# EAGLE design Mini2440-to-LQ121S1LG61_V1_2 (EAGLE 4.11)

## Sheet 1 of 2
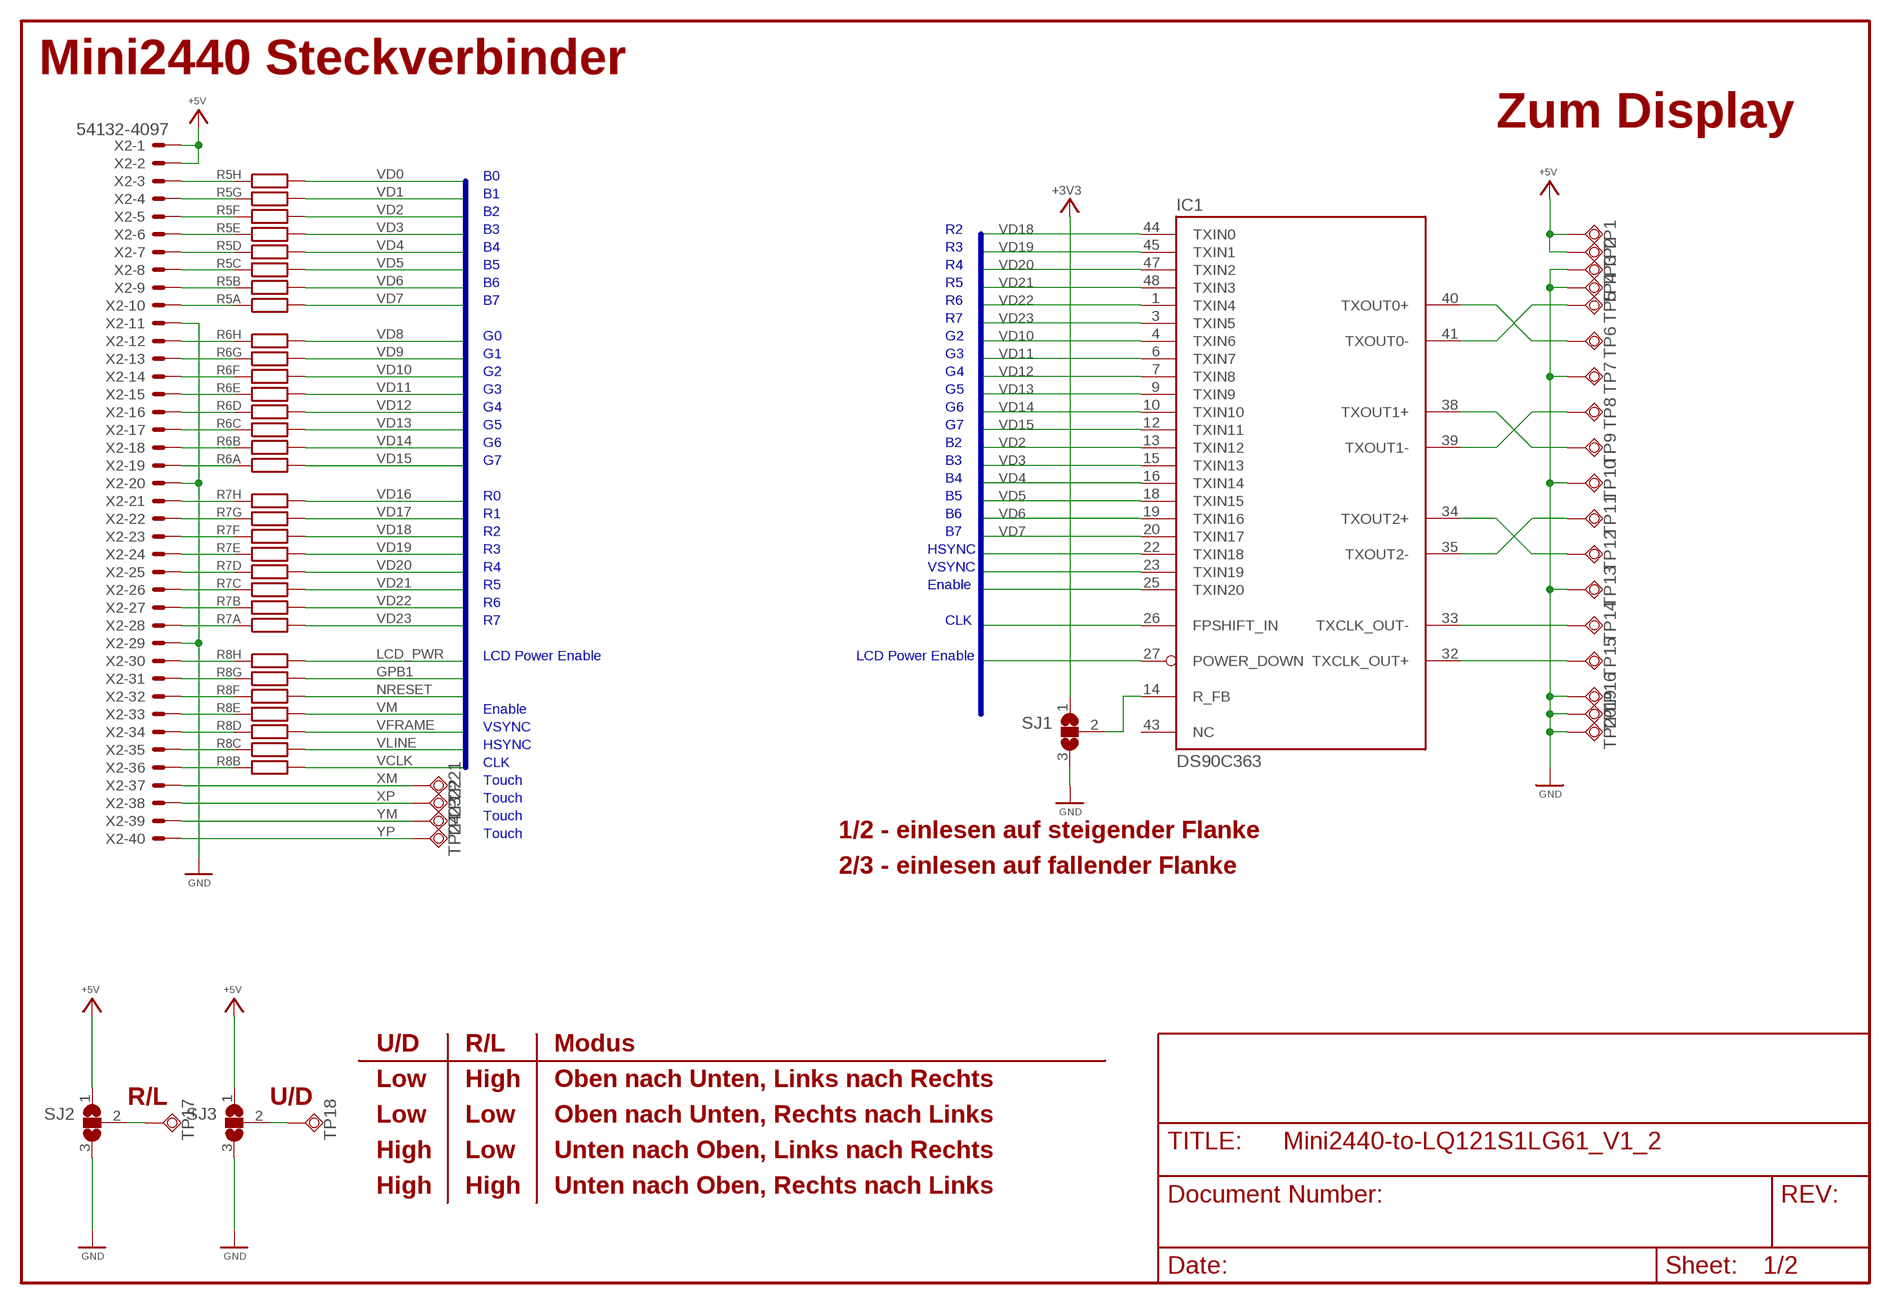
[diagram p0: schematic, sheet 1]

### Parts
IC1  DS90C363  [TSSOP48]
R5  R-8X0402  [YC248]
R6  R-8X0402  [YC248]
R7  R-8X0402  [YC248]
R8  R-8X0402  [YC248]
SJ1  SJ2WS  [SJ_2S]
SJ2  SJ2WS  [SJ_2S]
SJ3  SJ2WS  [SJ_2S]
TP1  TPSQTP15R  [TP15R]
TP2  TPSQTP15R  [TP15R]
TP3  TPSQTP15R  [TP15R]
TP4  TPSQTP15R  [TP15R]
TP5  TPSQTP15R  [TP15R]
TP6  TPSQTP15R  [TP15R]
TP7  TPSQTP15R  [TP15R]
TP8  TPSQTP15R  [TP15R]
TP9  TPSQTP15R  [TP15R]
TP10  TPSQTP15R  [TP15R]
TP11  TPSQTP15R  [TP15R]
TP12  TPSQTP15R  [TP15R]
TP13  TPSQTP15R  [TP15R]
TP14  TPSQTP15R  [TP15R]
TP15  TPSQTP15R  [TP15R]
TP16  TPSQTP15R  [TP15R]
TP17  TPSQTP15R  [TP15R]
TP18  TPSQTP15R  [TP15R]
TP19  TPSQTP15R  [TP15R]
TP20  TPSQTP15R  [TP15R]
TP21  TPSQTP12R  [TP12R]
TP22  TPSQTP12R  [TP12R]
TP23  TPSQTP12R  [TP12R]
TP24  TPSQTP12R  [TP12R]
X2  54132-4097  [54132-4097]

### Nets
+3V3: SJ1.1 ; also sheet 2
+5V: SJ2.1 SJ3.1 TP1.TP TP2.TP X2.1 X2.2 ; also sheet 2
GND: SJ1.3 SJ2.3 SJ3.3 TP3.TP TP4.TP TP7.TP TP10.TP TP13.TP TP16.TP TP19.TP TP20.TP X2.11 X2.20 X2.29 ; also sheet 2
GPB1: R8.10
LCD_PWR: IC1.27(POWER_DOWN) R8.9
N$1: IC1.41(TXOUT0-) TP5.TP
N$2: IC1.40(TXOUT0+) TP6.TP
N$3: IC1.39(TXOUT1-) TP8.TP
N$4: IC1.38(TXOUT1+) TP9.TP
N$5: IC1.35(TXOUT2-) TP11.TP
N$6: IC1.34(TXOUT2+) TP12.TP
N$7: IC1.33(TXCLK_OUT-) TP14.TP
N$8: IC1.32(TXCLK_OUT+) TP15.TP
N$9: R5.1 X2.10
N$11: R5.2 X2.9
N$12: R5.3 X2.8
N$13: R5.4 X2.7
N$14: R5.5 X2.6
N$15: R5.6 X2.5
N$16: R5.7 X2.4
N$17: R5.8 X2.3
N$18: R6.8 X2.12
N$19: R6.7 X2.13
N$20: R6.6 X2.14
N$21: R6.4 X2.16
N$22: R6.5 X2.15
N$23: R6.3 X2.17
N$24: R6.1 X2.19
N$25: R6.2 X2.18
N$26: R7.8 X2.21
N$27: R7.7 X2.22
N$28: R7.6 X2.23
N$29: R7.5 X2.24
N$30: R7.4 X2.25
N$31: R7.3 X2.26
N$32: R7.2 X2.27
N$33: R7.1 X2.28
N$34: R8.8 X2.30
N$35: R8.7 X2.31
N$36: R8.6 X2.32
N$37: R8.5 X2.33
N$38: R8.4 X2.34
N$39: R8.3 X2.35
N$40: R8.2 X2.36
N$45: IC1.14(R_FB) SJ1.2
N$46: SJ2.2 TP17.TP
N$47: SJ3.2 TP18.TP
NRESET: R8.11
VCLK: IC1.26(FPSHIFT_IN) R8.15
VD0: R5.9
VD1: R5.10
VD2: IC1.13(TXIN12) R5.11
VD3: IC1.15(TXIN13) R5.12
VD4: IC1.16(TXIN14) R5.13
VD5: IC1.18(TXIN15) R5.14
VD6: IC1.19(TXIN16) R5.15
VD7: IC1.20(TXIN17) R5.16
VD8: R6.9
VD9: R6.10
VD10: IC1.4(TXIN6) R6.11
VD11: IC1.6(TXIN7) R6.12
VD12: IC1.7(TXIN8) R6.13
VD13: IC1.9(TXIN9) R6.14
VD14: IC1.10(TXIN10) R6.15
VD15: IC1.12(TXIN11) R6.16
VD16: R7.9
VD17: R7.10
VD18: IC1.44(TXIN0) R7.11
VD19: IC1.45(TXIN1) R7.12
VD20: IC1.47(TXIN2) R7.13
VD21: IC1.48(TXIN3) R7.14
VD22: IC1.1(TXIN4) R7.15
VD23: IC1.3(TXIN5) R7.16
VFRAME: IC1.23(TXIN19) R8.13
VLINE: IC1.22(TXIN18) R8.14
VM: IC1.25(TXIN20) R8.12
XM: TP21.TP X2.37
XP: TP22.TP X2.38
YM: TP23.TP X2.39
YP: TP24.TP X2.40
Unconnected: R8.1 R8.16

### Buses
VD[0..23],VM,VFRAME,VLINE,VCLK,XM,XP,YM,YP,GPB1,NRESET,LCD_PWR

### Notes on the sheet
- Mini2440 Steckverbinder
- Zum Display
- B0
- B1
- B2
- B3 | R2
- B4 | R3
- B5 | R4
- B6 | R5
- B7 | R6
- R7
- G0 | G2
- G1 | G3
- G2 | G4
- G3 | G5
- G4 | G6
- G5 | G7
- G6 | B2
- G7 | B3
- B4
- R0 | B5
- R1 | B6
- R2 | B7
- R3 | HSYNC
- R4 | VSYNC
- R5 | Enable
- R6
- R7 | CLK
- LCD Power Enable | LCD Power Enable
- Enable
- VSYNC
- HSYNC
- CLK
- Touch
- Touch
- Touch
- Touch | 1/2 - einlesen auf steigender Flanke
- 2/3 - einlesen auf fallender Flanke
- U/D | R/L | Modus
- Low | High | Oben nach Unten, Links nach Rechts
- R/L | U/D
- Low | Low | Oben nach Unten, Rechts nach Links
- High | Low | Unten nach Oben, Links nach Rechts
- High | High | Unten nach Oben, Rechts nach Links

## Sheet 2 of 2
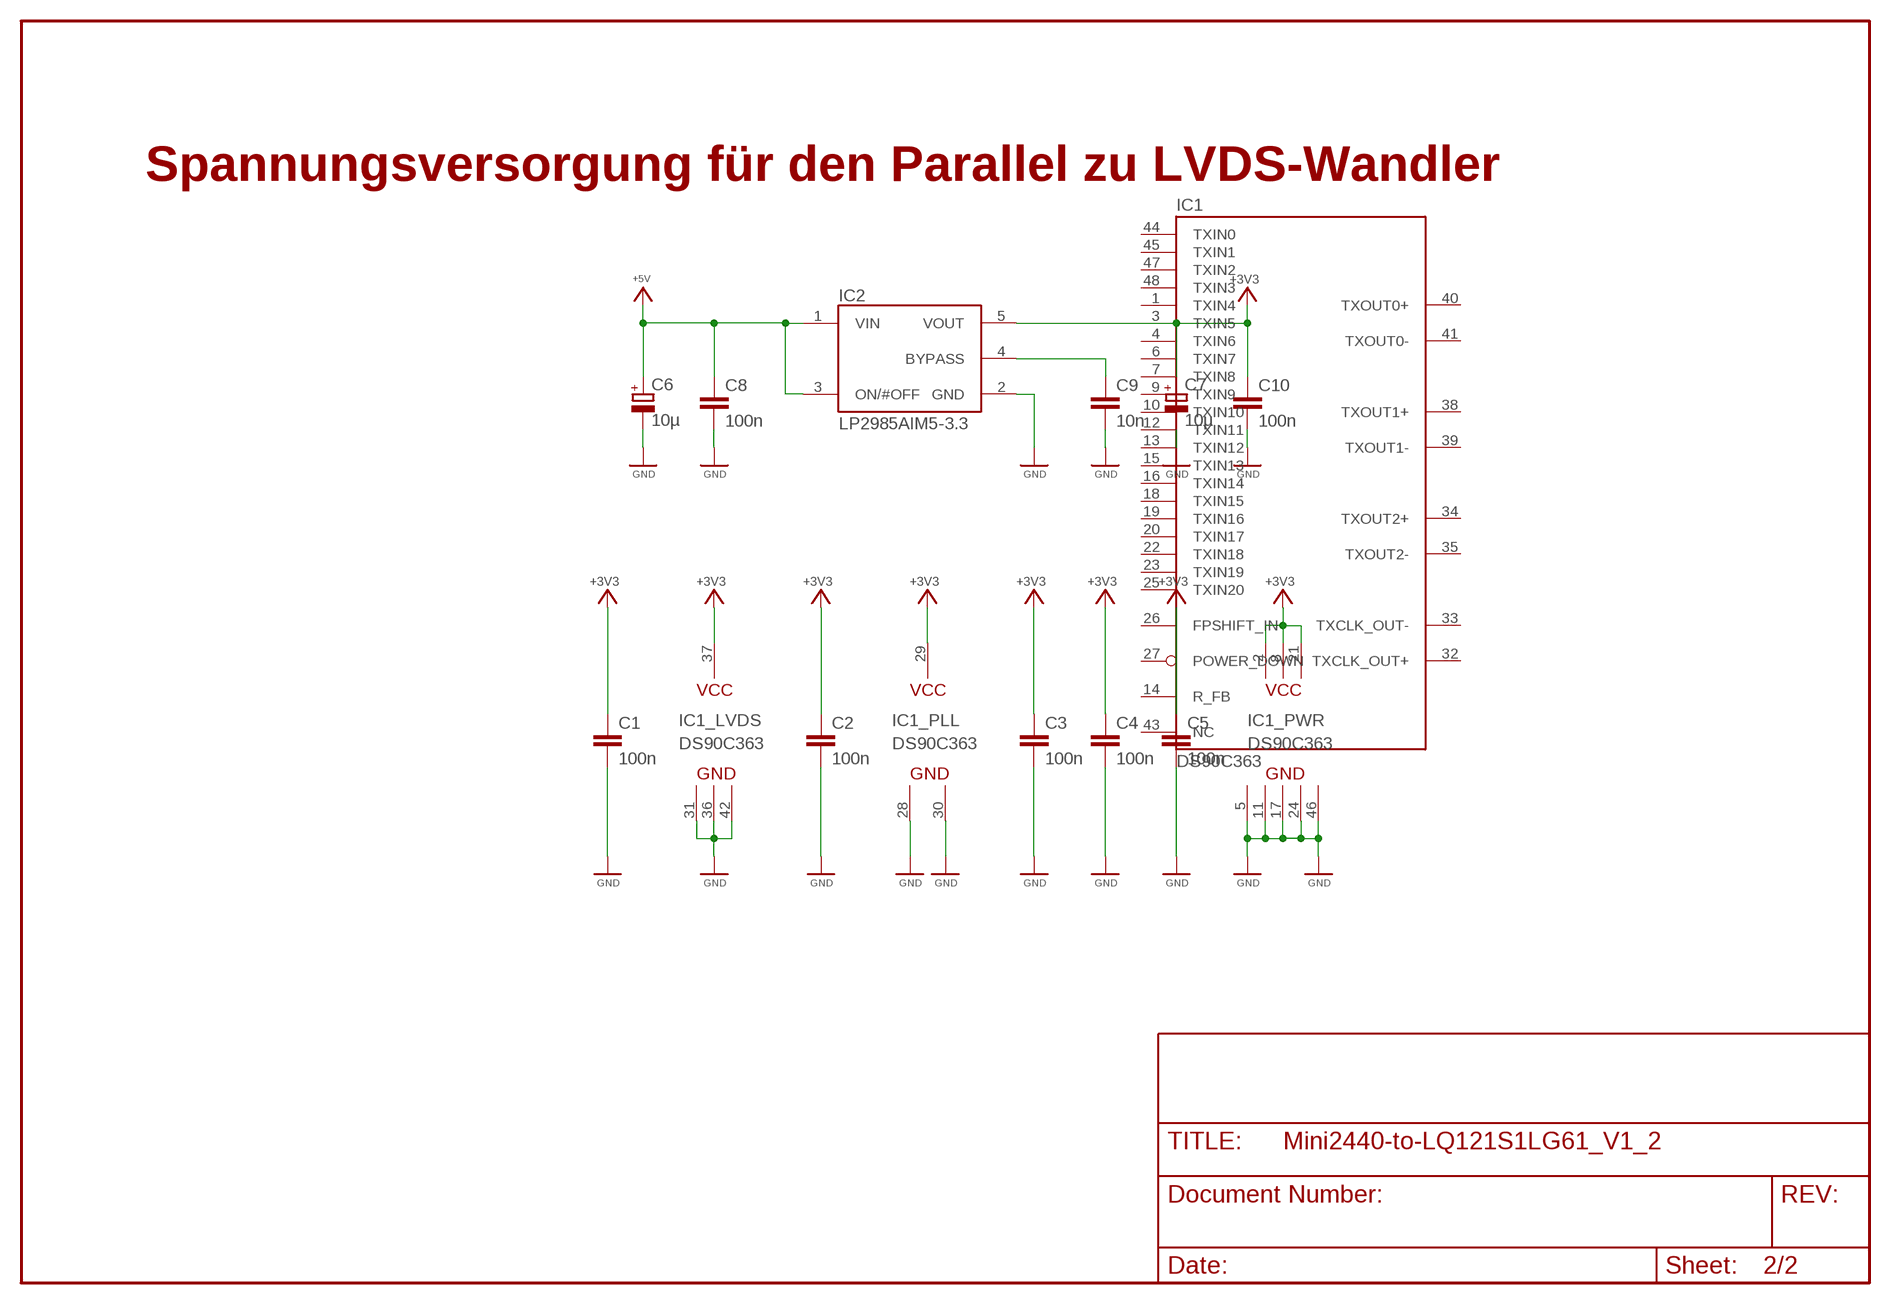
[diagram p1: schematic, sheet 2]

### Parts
C1  100n  C-EUC0603K  [C0603K]
C2  100n  C-EUC0603K  [C0603K]
C3  100n  C-EUC0603K  [C0603K]
C4  100n  C-EUC0603K  [C0603K]
C5  100n  C-EUC0603K  [C0603K]
C6  10µ  CPOL-EUB/3528-21R  [B/3528-21R]
C7  10µ  CPOL-EUB/3528-21R  [B/3528-21R]
C8  100n  C-EUC0603K  [C0603K]
C9  10n  C-EUC0603K  [C0603K]
C10  100n  C-EUC0603K  [C0603K]
IC2  LP2985AIM5-3.3  LP2985AIM5  [SOT23-5L]

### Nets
+3V3: C1.1 C2.1 C3.1 C4.1 C5.1 C7.+ C10.1 IC1.2(VCC) IC1.8(VCC) IC1.21(VCC) IC1.29(PVCC1) IC1.37(LVCC) IC2.5(VOUT) ; also sheet 1
+5V: C6.+ C8.1 IC2.1(VIN) IC2.3(ON/#OFF) ; also sheet 1
GND: C1.2 C2.2 C3.2 C4.2 C5.2 C6.- C7.- C8.2 C9.2 C10.2 IC1.5(GND) IC1.11(GND) IC1.17(GND) IC1.24(GND) IC1.28(PGND) IC1.30(PGND) IC1.31(LGND) IC1.36(LGND) IC1.42(LGND) IC1.46(GND) IC2.2(GND) ; also sheet 1
N$10: C9.1 IC2.4(BYPASS)
Unconnected: IC1.43(NC)

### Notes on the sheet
- Spannungsversorgung für den Parallel zu LVDS-Wandler

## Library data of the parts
C1-C5 C8-C10 = rcl:C-EU: CAPACITOR, European symbol
C6 C7 = rcl:CPOL-EU: POLARIZED CAPACITOR, European symbol
IC1 = JEK-National:DS90C363
IC2 = JEK-National:LP2985
R5-R8 = JEK-Resistor-Array:R-8X0402
SJ1-SJ3 = jumper:SJ2W: SMD solder JUMPER
TP1-TP24 = testpad:TPSQ
X2 = con-molex:54132-4097

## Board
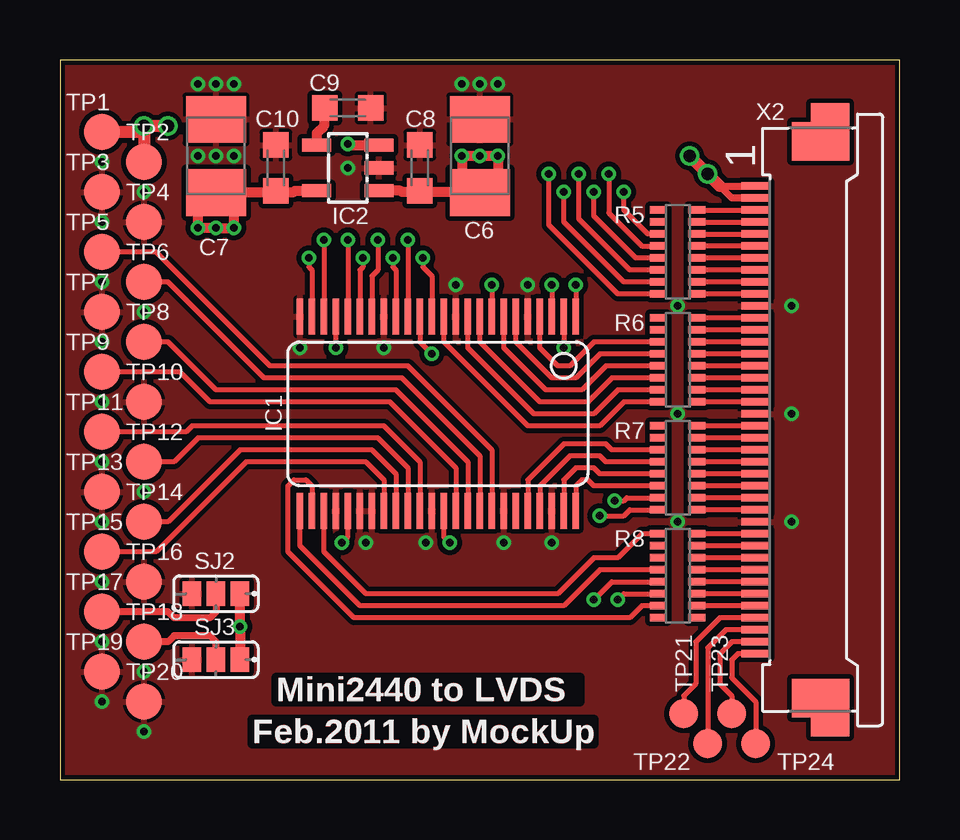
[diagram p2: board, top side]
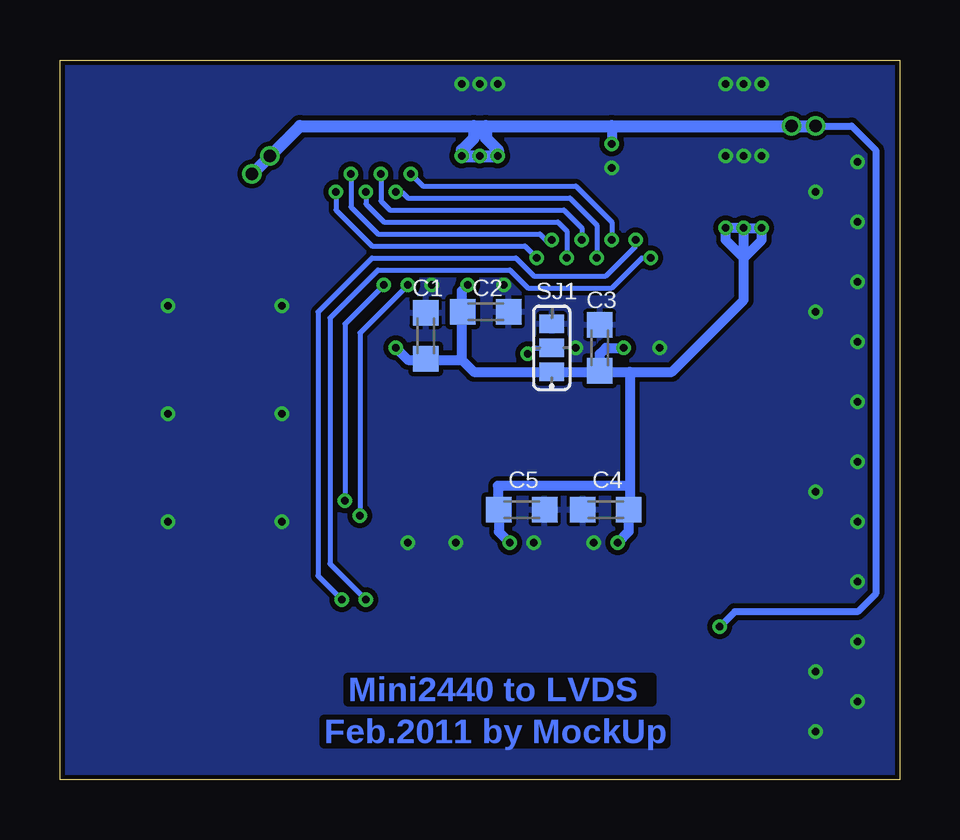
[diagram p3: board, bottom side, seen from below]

Size 35 x 30 mm. Coordinates in mm from the lower left corner, seen from the top.
Outline: 35,30 0,30 0,0 35,0 35,30
Copper layers (1*16): Top 0.035mm / dielectric 1.5mm / Bottom 0.035mm
Design rules "2layerJakob": minimum track width 0.15mm, minimum drill 0.3mm, track to track 0.15mm, track to pad 0.15mm, pad to pad 0.15mm, via to via 0.15mm, smd to smd 0.15mm, copper to edge 0.15mm, drill to drill 0.2mm, minimum pad ring 0.15mm, minimum via ring 0.15mm, stop-mask expansion 0.15mm, vias tented up to drill 0.35mm, thermal gap 0.15mm

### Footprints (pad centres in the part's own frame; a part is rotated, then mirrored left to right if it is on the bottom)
C0603K = smd 1.05 x 1.08: 1 -0.954,0; 2 0.954,0
B/3528-21R = smd 1.95 x 2.5: + 1.525,0; - -1.525,0
TSSOP48 = smd 0.254 x 1.5: 1 -5.75,-4.05; 2 -5.25,-4.05; 3 -4.75,-4.05; 4 -4.25,-4.05; 5 -3.75,-4.05; 6 -3.25,-4.05; 7 -2.75,-4.05; 8 -2.25,-4.05; 9 -1.75,-4.05; 10 -1.25,-4.05; 11 -0.75,-4.05; 12 -0.25,-4.05; 13 0.25,-4.05; 14 0.75,-4.05; 15 1.25,-4.05; 16 1.75,-4.05; 17 2.25,-4.05; 18 2.75,-4.05; 19 3.25,-4.05; 20 3.75,-4.05; 21 4.25,-4.05; 22 4.75,-4.05; 23 5.25,-4.05; 24 5.75,-4.05; 25 5.75,4.05; 26 5.25,4.05; 27 4.75,4.05; 28 4.25,4.05; 29 3.75,4.05; 30 3.25,4.05; 31 2.75,4.05; 32 2.25,4.05; 33 1.75,4.05; 34 1.25,4.05; 35 0.75,4.05; 36 0.25,4.05; 37 -0.25,4.05; 38 -0.75,4.05; 39 -1.25,4.05; 40 -1.75,4.05; 41 -2.25,4.05; 42 -2.75,4.05; 43 -3.25,4.05; 44 -3.75,4.05; 45 -4.25,4.05; 46 -4.75,4.05; 47 -5.25,4.05; 48 -5.75,4.05
SOT23-5L = smd 0.55 x 1.2: 1 -0.95,-1.3; 2 0,-1.3; 3 0.95,-1.3; 4 0.95,1.3; 5 -0.95,1.3
YC248 = smd 0.3 x 0.7: 1 -1.75,-0.8; 2 -1.25,-0.8; 3 -0.75,-0.8; 4 -0.25,-0.8; 5 0.25,-0.8; 6 0.75,-0.8; 7 1.25,-0.8; 8 1.75,-0.8; 9 1.75,0.8; 10 1.25,0.8; 11 0.75,0.8; 12 0.25,0.8; 13 -0.25,0.8; 14 -0.75,0.8; 15 -1.25,0.8; 16 -1.75,0.8
SJ_2S = smd 0.762 x 1.016: 1 -1,0; 2 0,0; 3 1,0
TP15R = smd 1.5 x 1.5: TP 0,0
TP12R = smd 1.2 x 1.2: TP 0,0
54132-4097 = smd 0.3 x 1.2: 1 9.75,0; 2 9.25,0; 3 8.75,0; 4 8.25,0; 5 7.75,0; 6 7.25,0; 7 6.75,0; 8 6.25,0; 9 5.75,0; 10 5.25,0; 11 4.75,0; 12 4.25,0; 13 3.75,0; 14 3.25,0; 15 2.75,0; 16 2.25,0; 17 1.75,0; 18 1.25,0; 19 0.75,0; 20 0.25,0; 21 -0.25,0; 22 -0.75,0; 23 -1.25,0; 24 -1.75,0; 25 -2.25,0; 26 -2.75,0; 27 -3.25,0; 28 -3.75,0; 29 -4.25,0; 30 -4.75,0; 31 -5.25,0; 32 -5.75,0; 33 -6.25,0; 34 -6.75,0; 35 -7.25,0; 36 -7.75,0; 37 -8.25,0; 38 -8.75,0; 39 -9.25,0; 40 -9.75,0 | smd 2.4 x 1.6: P$1 -12,-3.1; P$3 12,-3.1 | smd 1.6 x 0.8: P$2 -11.6,-1.9; P$4 11.6,-1.9

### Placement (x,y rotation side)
C1  19.75,18.5 90 bottom
C2  17.25,19.5 0 bottom
C3  12.5,18 90 bottom
C4  12.25,11.25 180 bottom
C5  15.75,11.25 0 bottom
C6  17.5,26 270 top
C7  6.5,26 270 top
C8  15,25.5 90 top
C9  12,28 0 top
C10  9,25.5 90 top
IC1  15.75,15.25 180 top
IC2  12,25.5 90 top
R5  25.75,22 90 top
R6  25.75,17.5 90 top
R7  25.75,13 90 top
R8  25.75,8.5 90 top
SJ1  14.5,18 90 bottom
SJ2  6.5,7.75 180 top
SJ3  6.5,5 180 top
TP1  1.75,27 0 top
TP2  3.5,25.75 0 top
TP3  1.75,24.5 0 top
TP4  3.5,23.25 0 top
TP5  1.75,22 0 top
TP6  3.5,20.75 0 top
TP7  1.75,19.5 0 top
TP8  3.5,18.25 0 top
TP9  1.75,17 0 top
TP10  3.5,15.75 0 top
TP11  1.75,14.5 0 top
TP12  3.5,13.25 0 top
TP13  1.75,12 0 top
TP14  3.5,10.75 0 top
TP15  1.75,9.5 0 top
TP16  3.5,8.25 0 top
TP17  1.75,7 0 top
TP18  3.5,5.75 0 top
TP19  1.75,4.5 0 top
TP20  3.5,3.25 0 top
TP21  26,2.75 0 top
TP22  27,1.5 0 top
TP23  28,2.75 0 top
TP24  29,1.5 0 top
X2  29,15 90 top

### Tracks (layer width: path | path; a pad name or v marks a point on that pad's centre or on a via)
+3V3  (via drill 0.3)
  Top 0.203: IC1.2 v21,18 | IC1.37 16,10.12 v16.25,9.88 | IC1.29 12,10.12 v11.75,9.88 | v11.5,18 IC1.21 | v18,20.62 IC1.8
  Top 0.406: IC2.5 9.8,24.55 9.75,24.5 9,24.5 | 9,24.5 C10.1 | 7.25,24.5 6.5,24.5 C7.+ 6.23,24.48 5.75,24 v5.75,23 v6.5,23 v7.25,23 7.25,24.5 | 7.25,24.5 9,24.5
  Bottom 0.406: v11.75,9.88 11.3,10.33 C4.1 11.25,11.25 11.25,12.25 | v16.25,9.88 16.7,10.33 C5.1 16.75,11.25 16.75,12.25 11.25,12.25 | 12.5,17 SJ1.1 17.75,17 18.25,17.5 | 19.75,17.5 18.25,17.5 | 19.75,17.5 C1.1 | 19.75,17.5 20.5,17.5 v21,18 | 18.25,17.5 18.25,19.5 | 18.25,19.5 C2.1 | v18,20.62 18.25,20.38 18.25,19.5 | 11.25,17 11.25,12.25 | 12.5,17 11.25,17 | 12.5,17 C3.1 | 12.5,17 12.5,17.75 12.25,18 v11.5,18 | 11.25,17 9.5,17 6.5,20 6.5,21.75 | v6.5,23 v5.75,23 5.75,22.5 6.5,21.75 | v6.5,23 v7.25,23 7.25,22.5 6.5,21.75 | 6.5,21.75 v6.5,23
+5V  (via drill 0.3, 0.51)
  Top 0.3: X2.2 28,24.25 27.5,24.75 X2.1
  Top 0.406: IC2.1 14.2,24.55 14.25,24.5 15,24.5 | 15,24.5 C8.1 | 17.5,24.5 C6.+ | 16.75,24.5 17.5,24.5 | 16.75,24.5 15,24.5 | IC2.3 12.05,26.45 v12,26.5 | SJ2.1 v7.5,6.38 SJ3.1 | 16.75,24.5 v16.75,26 v17.5,26 v18.25,26 18.25,24.5 17.5,24.5
  Top 0.508: v3.5,27.25 3.25,27 TP1.TP | v3.5,27.25 TP2.TP | v4.5,27.25 v3.5,27.25 | v26.25,26 v27,25.25 27.5,24.75
  Bottom 0.3: v3.5,27.25 2,27.25 1,26.25 1,7.75 1.75,7 6.88,7 v7.5,6.38
  Bottom 0.406: 12,27.25 v12,26.5
  Bottom 0.508: 17.25,27.25 12,27.25 v4.5,27.25 v3.5,27.25 | 17.75,27.25 17.25,27.25 | 17.75,27.25 25,27.25 v26.25,26 v27,25.25 | 17.25,27.25 17.25,26.75 16.75,26.25 v16.75,26 v17.5,26 v18.25,26 18.25,26.25 17.75,26.75 17.75,27.25
GND  (via drill 0.3)
  other vias: 30.5,19.75 30.5,15.25 30.5,10.75 25.75,15.25 25.75,19.75 25.75,10.75 13.5,18 10,18 12.75,9.88 15.25,9.88 18.5,9.88 20.5,9.88 16.5,20.62 19.5,20.62 6.5,26 7.25,26 5.75,26 17.5,29 16.75,29 18.25,29 12,25.5 5.75,29 6.5,29 7.25,29 1.75,25.75 1.75,23.25 3.5,24.5 1.75,20.75 3.5,19.5 1.75,18.25 1.75,15.75 1.75,13.25 3.5,12 1.75,10.75 1.75,8.25 1.75,5.75 3.5,4.5 1.75,3.25 3.5,2
  pour Top (isolate 0.2): 0,30 0,0 35,0 35,30
  pour Bottom (isolate 0.2): 0,30 0,0 35,0 35,30
LCD_PWR
  Top 0.203: R8.9 24.25,10.25 23.25,9.25 22.25,9.25 20.75,7.75 12.75,7.75 11,9.5 IC1.27
N$1
  Top 0.203: IC1.41 18,13.75 14.5,17.25 8.75,17.25 4,22 TP5.TP
N$2
  Top 0.203: IC1.40 17.5,13.5 14.25,16.75 8.5,16.75 4.5,20.75 TP6.TP
N$3
  Top 0.203: IC1.39 17,13.25 14,16.25 6.5,16.25 4.5,18.25 TP8.TP
N$4
  Top 0.203: IC1.38 16.5,13 13.75,15.75 6.25,15.75 5,17 TP9.TP
N$5
  Top 0.203: IC1.35 15,13.25 13.5,14.75 5.5,14.75 5.25,14.5 TP11.TP
N$6
  Top 0.203: IC1.34 14.5,13 13.25,14.25 5.75,14.25 4.75,13.25 TP12.TP
N$7
  Top 0.203: IC1.33 14,12.75 13,13.75 7.5,13.75 4.5,10.75 TP14.TP
N$8
  Top 0.203: IC1.32 13.5,12.5 12.75,13.25 7.75,13.25 4,9.5 TP15.TP
N$9
  Top 0.203: X2.10 R5.1
N$10
  Top 0.406: IC2.4 10.7,26.95 11,27.25 11,28 C9.1
N$11
  Top 0.203: X2.9 R5.2
N$12
  Top 0.203: X2.8 R5.3
N$13
  Top 0.203: X2.7 R5.4
N$14
  Top 0.203: X2.6 R5.5
N$15
  Top 0.203: R5.6 X2.5
N$16
  Top 0.203: R5.7 X2.4
N$17
  Top 0.203: R5.8 X2.3
N$18
  Top 0.203: X2.12 R6.8
N$19
  Top 0.203: X2.13 R6.7
N$20
  Top 0.203: X2.14 R6.6
N$21
  Top 0.203: X2.16 R6.4
N$22
  Top 0.203: X2.15 R6.5
N$23
  Top 0.203: X2.17 R6.3
N$24
  Top 0.203: X2.19 R6.1
N$25
  Top 0.203: X2.18 R6.2
N$26
  Top 0.203: X2.21 R7.8
N$27
  Top 0.203: X2.22 R7.7
N$28
  Top 0.203: X2.23 R7.6
N$29
  Top 0.203: X2.24 R7.5
N$30
  Top 0.203: X2.25 R7.4
N$31
  Top 0.203: X2.26 R7.3
N$32
  Top 0.203: X2.27 R7.2
N$33
  Top 0.203: X2.28 R7.1
N$34
  Top 0.203: X2.30 R8.8
N$35
  Top 0.203: X2.31 R8.7
N$36
  Top 0.203: X2.32 R8.6
N$37
  Top 0.203: X2.33 R8.5
N$38
  Top 0.203: X2.34 R8.4
N$39
  Top 0.203: X2.35 R8.3
N$40
  Top 0.203: X2.36 R8.2
N$45  (via drill 0.3)
  Top 0.203: IC1.14 15,18.25 v15.5,17.75
  Bottom 0.203: v15.5,17.75 15.25,18 SJ1.2
N$46
  Top 0.3: TP17.TP 4.5,7 4.75,6.75 6.25,6.75 6.5,7 SJ2.2
N$47
  Top 0.3: TP18.TP 4.5,5.75 4.75,6 6.25,6 6.5,5.75 SJ3.2
VCLK
  Top 0.203: R8.15 24.25,7.25 23.75,6.75 12.25,6.75 9.5,9.5 9.5,12.25 9.75,12.5 10.25,12.5 10.5,12.25 IC1.26
VD2  (via drill 0.3)
  Top 0.203: R5.11 24.5,22.75 23.5,23.75 v23.5,24.5 | v15.12,21.75 15.12,21.38 15.5,21 IC1.13
  Bottom 0.203: v23.5,24.5 23.5,23.75 22,22.25 15.62,22.25 v15.12,21.75
VD3  (via drill 0.3)
  Top 0.203: R5.12 24.25,22.25 22.88,23.62 v22.88,25.25 | v14.5,22.5 IC1.15
  Bottom 0.203: v22.88,25.25 22.88,23.88 21.75,22.75 15,22.75 14.75,22.5 v14.5,22.5
VD4  (via drill 0.3)
  Top 0.203: R5.13 24,21.75 22.25,23.5 v22.25,24.5 | IC1.16 14,21.25 13.88,21.38 v13.88,21.75
  Bottom 0.203: v22.25,24.5 22.25,24 21.5,23.25 14.25,23.25 13.88,22.88 v13.88,21.75
VD5  (via drill 0.3)
  Top 0.203: R5.14 23.75,21.25 21.62,23.38 v21.62,25.25 | IC1.18 13,21 13.25,21.25 v13.25,22.5
  Bottom 0.203: v21.62,25.25 21.62,24.12 21.25,23.75 14,23.75 13.25,23 v13.25,22.5
VD6  (via drill 0.3)
  Top 0.203: R5.15 23.5,20.75 21,23.25 v21,24.5 | IC1.19 12.5,21.25 12.62,21.38 v12.62,21.75
  Bottom 0.203: v21,24.5 20.75,24.5 20.5,24.25 13.75,24.25 12.62,23.12 v12.62,21.75
VD7  (via drill 0.3)
  Top 0.203: R5.16 23.25,20.25 20.38,23.12 v20.38,25.25 | v12,22.5 IC1.20
  Bottom 0.203: v20.38,25.25 19.88,24.75 13.5,24.75 12,23.25 v12,22.5
VD10
  Top 0.203: R6.11 22.25,18.25 21.25,17.25 20.75,17.25 20,18 IC1.4
VD11
  Top 0.203: IC1.6 19,18.25 20.5,16.75 21.5,16.75 22.5,17.75 R6.12
VD12
  Top 0.203: IC1.7 18.5,18 20.25,16.25 21.75,16.25 22.75,17.25 R6.13
VD13
  Top 0.203: IC1.9 17.5,18.25 20,15.75 22,15.75 23,16.75 R6.14
VD14
  Top 0.203: IC1.10 17,18 19.75,15.25 22.25,15.25 23.25,16.25 R6.15
VD15
  Top 0.203: IC1.12 16,18.25 19.5,14.75 22.5,14.75 23.5,15.75 R6.16 25,15.75
VD18
  Top 0.203: IC1.44 19.5,12.5 21,14 22.75,14 23,13.75 R7.11
VD19
  Top 0.203: IC1.45 20,12.25 21.25,13.5 22.5,13.5 22.75,13.25 R7.12
VD20
  Top 0.203: IC1.47 21,12.5 21.5,13 22.25,13 22.5,12.75 R7.13
VD21
  Top 0.203: R7.14 22.25,12.25 22,12.5 21.75,12.5 21.5,12.25 IC1.48
VD22  (via drill 0.3)
  Top 0.203: v23.12,11.62 23.5,11.62 23.62,11.75 R7.15 | v21.5,20.62 IC1.1
  Bottom 0.203: v23.12,11.62 23.12,19 v21.5,20.62
VD23  (via drill 0.3)
  Top 0.203: R7.16 23.75,11.25 23.5,11 v22.5,11 | v20.5,20.62 IC1.3
  Bottom 0.203: v22.5,11 22.5,18.62 v20.5,20.62
VFRAME  (via drill 0.3)
  Top 0.203: v10.38,21.75 10.38,21.38 10.5,21.25 IC1.23 | v22.25,7.5 23,8.25 R8.13
  Bottom 0.203: v10.38,21.75 10.75,21.75 12,20.5 15.5,20.5 16.25,21.25 21.75,21.25 23.75,19.25 23.75,9 v22.25,7.5
VLINE  (via drill 0.3)
  Top 0.203: v11,22.5 IC1.22 | v23.25,7.5 23.5,7.75 R8.14
  Bottom 0.203: v11,22.5 11,22.25 12.25,21 15.25,21 16,21.75 22,21.75 24.25,19.5 24.25,8.5 v23.25,7.5
VM
  Top 0.203: R8.12 22.5,8.75 21,7.25 12.5,7.25 10,9.75 IC1.25
XM
  Top 0.203: X2.37 27.5,6.75 26.5,5.75 26.5,4 26,3.5 TP21.TP
XP
  Top 0.203: X2.38 27.75,6.25 27,5.5 TP22.TP
YM
  Top 0.203: X2.39 28,5.75 27.5,5.25 27.5,4 28,3.5 TP23.TP
YP
  Top 0.203: X2.40 28.25,5.25 28,5 28,4.25 29,3.25 TP24.TP

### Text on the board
Top: Mini2440 to LVDS | Feb.2011 by MockUp
Bottom: Mini2440 to LVDS | Feb.2011 by MockUp
tPlace: Mini2440 to LVDS | Feb.2011 by MockUp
